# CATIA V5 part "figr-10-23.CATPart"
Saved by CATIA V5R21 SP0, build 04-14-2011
Part number: Part1
Bounding box of the stored display mesh (mm): x -180.516 to 0, y -36.805 to 65.824, z 0 to 36.805
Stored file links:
  D:\CATIA V5R21 E-RESOURCES\CATIA-V5R21\catia-v5r21-prt\c10-catia-v5r20-prt\c10-catia-v5r21-figr-10-23.CATPart
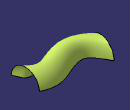
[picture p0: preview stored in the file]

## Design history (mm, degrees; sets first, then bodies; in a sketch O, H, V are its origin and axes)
Set1
  Sweep1: type Unspec, Profile Sketch2, Guide Sketch1
Body1 (main body)
  Sketch1 on xy-plane, origin (0, 0, 0), H (1, 0, 0), V (0, 1, 0)
    spline S1 through (0, 0) (-31.5913, 14.7273) (-94.8038, 0) (-174.5181, 29.5113)
    point P1 (0, 0)
    point P2 (-94.8038, 0)
    coincidence: P1 O, P2 H
  Sketch2 on yz-plane, origin (0, 0, 0), H (0, 1, 0), V (0, 0, 1)
    arc A1 centre (0, 0) radius 36.8048 from (36.8048, 0) to (-36.8048, 0) ccw
    point P1 (-36.8048, 0)
    point P2 (36.8048, 0)
    coincidence: P1 H, P2 H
